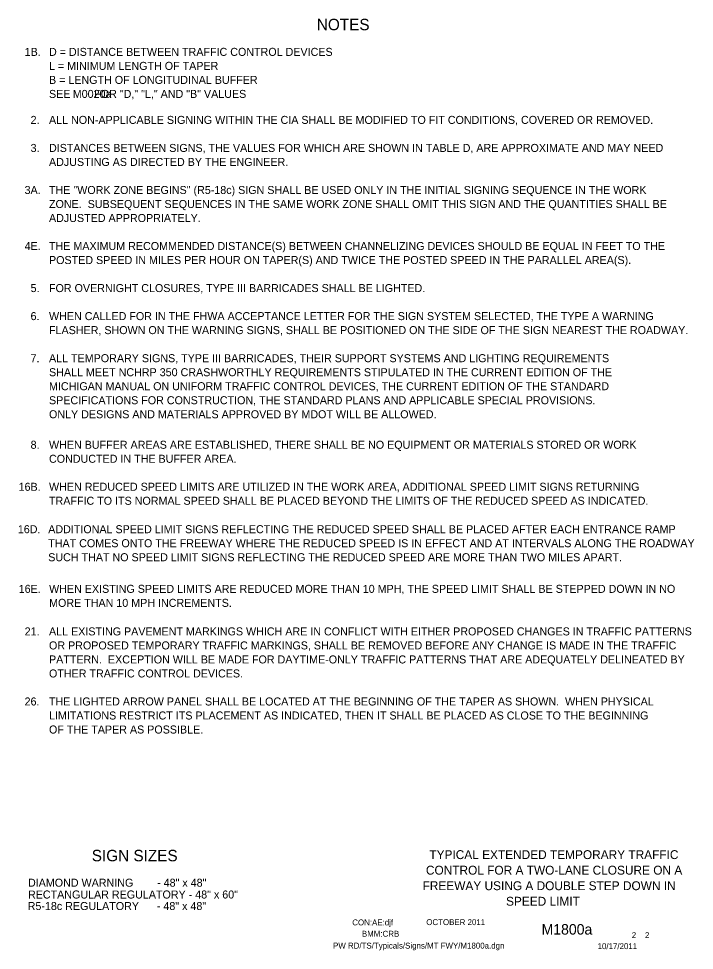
# Model space of a CAD drawing. Extents: x 16553 to 18478, y 5759 to 7026.
# Drawn here: x 17770 to 18478, y 5932 to 6909 of the extents above; entities that cross this region are included whole.
import ezdxf

# ---------------------------------------------------------------- set-up
doc = ezdxf.new("R2010")
doc.units = 0
for name, color, linetype in [('BORDER', 7, 'Continuous'), ('BORDER_SIGNAL_WO', 7, 'Continuous'), ('TYPICAL_TEXT_DIMEN_PR', 7, 'Continuous')]:
    doc.layers.add(name, color=color, linetype=linetype)

msp = doc.modelspace()

# ---------------------------------------------------------------- linework, layer by layer
at = {"layer": 'BORDER'}
msp.add_line((17909.25, 6035.02), (17909.25, 6035.02), dxfattribs=at)

# ---------------------------------------------------------------- texts
for s, p in [('TYPICAL EXTENDED TEMPORARY TRAFFIC', (18200.54, 6027.6)), ('CONTROL FOR A TWO-LANE CLOSURE ON A', (18196.92, 6011.3)), ('FREEWAY USING A DOUBLE STEP DOWN IN ', (18193.42, 5995)), ('SPEED LIMIT', (18280.92, 5978.7))]:
    msp.add_text(s, height=9.3, dxfattribs=at).set_placement(p)
at = {"layer": 'BORDER_SIGNAL_WO'}
for s, height, p in [('CON:AE:djf  ', 6.2, (18119.69, 5958.06)), ('    OCTOBER 2011', 6.2, (18188.08, 5958.34)), ('BMM:CRB', 6.2, (18129.81, 5946.17)), ('    M1800a   ', 11, (18301.86, 5948.38)), (' 2    2 ', 6.2, (18410.45, 5944.7)), ('PW RD/TS/Typicals/Signs/MT FWY/M1800a.dgn      ', 6.2, (18099.55, 5933.71)), ('10/17/2011', 6.2, (18376.93, 5933.13))]:
    msp.add_text(s, height=height, dxfattribs=at).set_placement(p)
at = {"layer": 'TYPICAL_TEXT_DIMEN_PR'}
for s, height, p in [('NOTES', 12, (18082.55, 6897)), ('1B.', 8.4, (17776.19, 6870.11)), ('D = DISTANCE BETWEEN TRAFFIC CONTROL DEVICES', 8.4, (17801.7, 6870.11)), ('L = MINIMUM LENGTH OF TAPER', 8.4, (17801.7, 6855.41)), ('B = LENGTH OF LONGITUDINAL BUFFER', 8.4, (17801.7, 6840.71)), ('SEE        FOR "D," "L," AND "B" VALUES', 8.4, (17801.7, 6826.01)), ('M0020a', 8.4, (17826.62, 6826.01)), ('2.', 8.4, (17782.39, 6798.75)), ('ALL NON-APPLICABLE SIGNING WITHIN THE CIA SHALL BE MODIFIED TO FIT CONDITIONS, COVERED OR REMOVED.', 8.4, (17801.7, 6798.75)), ('3.', 8.4, (17782.39, 6769.35)), ('DISTANCES BETWEEN SIGNS, THE VALUES FOR WHICH ARE SHOWN IN TABLE D, ARE APPROXIMATE AND MAY NEED', 8.4, (17801.7, 6769.35)), ('ADJUSTING AS DIRECTED BY THE ENGINEER.', 8.4, (17801.7, 6754.65)), ('THE "WORK ZONE BEGINS" (R5-18c) SIGN SHALL BE USED ONLY IN THE INITIAL SIGNING SEQUENCE IN THE WORK', 8.4, (17801.7, 6725.24)), ('3A.', 8.4, (17776.09, 6725.24)), ('ZONE.  SUBSEQUENT SEQUENCES IN THE SAME WORK ZONE SHALL OMIT THIS SIGN AND THE QUANTITIES SHALL BE', 8.4, (17801.7, 6710.54)), ('ADJUSTED APPROPRIATELY.', 8.4, (17801.7, 6695.84)), ('THE MAXIMUM RECOMMENDED DISTANCE(S) BETWEEN CHANNELIZING DEVICES SHOULD BE EQUAL IN FEET TO THE', 8.4, (17801.7, 6666.45)), ('4E.', 8.4, (17776.13, 6666.45)), ('POSTED SPEED IN MILES PER HOUR ON TAPER(S) AND TWICE THE POSTED SPEED IN THE PARALLEL AREA(S).', 8.4, (17801.7, 6651.75)), ('5.', 8.4, (17782.39, 6622.35)), ('FOR OVERNIGHT CLOSURES, TYPE III BARRICADES SHALL BE LIGHTED.', 8.4, (17801.7, 6622.35)), ('6.', 8.4, (17782.34, 6592.95)), ('WHEN CALLED FOR IN THE FHWA ACCEPTANCE LETTER FOR THE SIGN SYSTEM SELECTED, THE TYPE A WARNING ', 8.4, (17801.7, 6592.95)), ('FLASHER, SHOWN ON THE WARNING SIGNS, SHALL BE POSITIONED ON THE SIDE OF THE SIGN NEAREST THE ROADWAY.', 8.4, (17801.7, 6578.25)), ('7.', 8.4, (17782.34, 6548.77)), ('ALL TEMPORARY SIGNS, TYPE III BARRICADES, THEIR SUPPORT SYSTEMS AND LIGHTING REQUIREMENTS', 8.4, (17801.7, 6548.79)), ('SHALL MEET NCHRP 350 CRASHWORTHLY REQUIREMENTS STIPULATED IN THE CURRENT EDITION OF THE', 8.4, (17801.7, 6534.09)), ('MICHIGAN MANUAL ON UNIFORM TRAFFIC CONTROL DEVICES, THE CURRENT EDITION OF THE STANDARD', 8.4, (17801.7, 6519.39)), ('SPECIFICATIONS FOR CONSTRUCTION, THE STANDARD PLANS AND APPLICABLE SPECIAL PROVISIONS.', 8.4, (17801.7, 6504.69)), ('ONLY DESIGNS AND MATERIALS APPROVED BY MDOT WILL BE ALLOWED.', 8.4, (17801.7, 6489.99)), ('8.', 8.4, (17782.39, 6458)), ('WHEN BUFFER AREAS ARE ESTABLISHED, THERE SHALL BE NO EQUIPMENT OR MATERIALS STORED OR WORK     ', 8.4, (17801.7, 6458)), ('CONDUCTED IN THE BUFFER AREA.', 8.4, (17801.7, 6443.3)), ('16B.', 8.4, (17769.84, 6413.9)), ('WHEN REDUCED SPEED LIMITS ARE UTILIZED IN THE WORK AREA, ADDITIONAL SPEED LIMIT SIGNS RETURNING', 8.4, (17801.7, 6413.96)), ('TRAFFIC TO ITS NORMAL SPEED SHALL BE PLACED BEYOND THE LIMITS OF THE REDUCED SPEED AS INDICATED.', 8.4, (17801.7, 6399.26)), ('16D.', 8.4, (17769, 6369.41)), ('ADDITIONAL SPEED LIMIT SIGNS REFLECTING THE REDUCED SPEED SHALL BE PLACED AFTER EACH ENTRANCE RAMP', 8.4, (17800.87, 6369.41)), ('THAT COMES ONTO THE FREEWAY WHERE THE REDUCED SPEED IS IN EFFECT AND AT INTERVALS ALONG THE ROADWAY', 8.4, (17800.87, 6354.71)), ('SUCH THAT NO SPEED LIMIT SIGNS REFLECTING THE REDUCED SPEED ARE MORE THAN TWO MILES APART.', 8.4, (17800.87, 6340.01)), ('16E.', 8.4, (17769.92, 6306.86)), ('WHEN EXISTING SPEED LIMITS ARE REDUCED MORE THAN 10 MPH, THE SPEED LIMIT SHALL BE STEPPED DOWN IN NO', 8.4, (17801.79, 6306.86)), ('MORE THAN 10 MPH INCREMENTS.', 8.4, (17801.79, 6292.16)), ('21.', 8.4, (17776.14, 6262.21)), ('ALL EXISTING PAVEMENT MARKINGS WHICH ARE IN CONFLICT WITH EITHER PROPOSED CHANGES IN TRAFFIC PATTERNS', 8.4, (17801.7, 6262.21)), ('OR PROPOSED TEMPORARY TRAFFIC MARKINGS, SHALL BE REMOVED BEFORE ANY CHANGE IS MADE IN THE TRAFFIC', 8.4, (17801.7, 6247.51)), ('PATTERN.  EXCEPTION WILL BE MADE FOR DAYTIME-ONLY TRAFFIC PATTERNS THAT ARE ADEQUATELY DELINEATED BY', 8.4, (17801.7, 6232.81)), ('OTHER TRAFFIC CONTROL DEVICES.', 8.4, (17801.7, 6218.11)), ('26.', 8.4, (17776.09, 6188.71)), ('THE LIGHTED ARROW PANEL SHALL BE LOCATED AT THE BEGINNING OF THE TAPER AS SHOWN.  WHEN PHYSICAL', 8.4, (17801.7, 6188.71)), ('LIMITATIONS RESTRICT ITS PLACEMENT AS INDICATED, THEN IT SHALL BE PLACED AS CLOSE TO THE BEGINNING', 8.4, (17801.7, 6174.01)), ('OF THE TAPER AS POSSIBLE.', 8.4, (17801.7, 6159.31)), ('SIGN SIZES', 12, (17846.54, 6025.28)), ('DIAMOND WARNING        - 48" x 48"', 8.4, (17779.65, 5998.62)), ('RECTANGULAR REGULATORY - 48" x 60"', 8.4, (17779.65, 5986.22)), ('R5-18c REGULATORY      - 48" x 48"', 8.4, (17779.34, 5974.14))]:
    msp.add_text(s, height=height, dxfattribs=at).set_placement(p)

doc.saveas('drawing.dxf')
